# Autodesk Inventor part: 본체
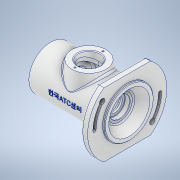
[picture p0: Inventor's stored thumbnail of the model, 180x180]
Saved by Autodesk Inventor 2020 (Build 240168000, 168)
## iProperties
Created: 2022-05
Part Number: 본체
Material: 알루미늄 6061
Document SubType Name: Modeling
Designer: Student
Density: 2.7 g/cm^3
Appearance: 알루미늄 - 평지
Mass: 694.173 g
Surface Area: 619.363 cm^2
Volume: 257.101 cm^3
Author: Student
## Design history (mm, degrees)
sketch "스케치1"
  geometry: L1 (-108.341, 0)-(108.341, 0); L2 (-56, 22.5)-(-48, 22.5); L3 (-48, 22.5)-(-48, 24); L4 (-48, 24)-(-45, 24); L5 (-45, 24)-(-45, 22.5); L6 (-45, 22.5)-(-34, 22.5); L7 (-34, 22.5)-(-34, 17.5); L8 (-34, 17.5)-(-31.75, 17.5); L9 (-31.75, 17.5)-(-31.75, 18.5); L10 (-31.75, 18.5)-(-30, 18.5); L11 (-30, 18.5)-(-30, 17.5); L12 (-30, 17.5)-(-19, 17.5); L13 (-19, 17.5)-(-19, 27); L14 (-19, 27)-(19, 27); L15 (19, 27)-(19, 17.5); L16 (19, 17.5)-(30, 17.5); L17 (30, 17.5)-(30, 15); L18 (30, 15)-(35, 15); L19 (35, 15)-(35, 11); L20 (35, 11)-(37.7, 11); L21 (37.7, 11)-(37.7, 15); L22 (37.7, 15)-(45, 15); L23 (46, 32)-(-56, 32); L24 (-56, 32)-(-56, 22.5); L25 (46, 32)-(46, 58); L26 (46, 58)-(56, 58); L27 (56, 58)-(56, 36); L28 (56, 36)-(59, 36); L29 (59, 36)-(59, 30); L30 (59, 30)-(45, 20); L31 (45, 20)-(45, 15); 3 further points
  constraints: 62 end point, 23 perpendicular, 4 point on line, 2 horizontal, 2 midpoint, 2 vertical, 1 coincident, 1 vertical alignment
  dimensions: "d1" = 45 diameter of L2 L1; "d2" = 48 diameter of L4 L1; "d3" = 45 diameter of L6 L1; "d4" = 35 diameter of L8 L1; "d5" = 37 diameter of L10 L1; "d6" = 54 diameter of L14 L1; "d7" = 30 diameter of L18 L1; "d8" = 22 diameter of L20 L1; "d9" = 30 diameter of L22 L1; "d10" = 64 diameter of L23 L1; "d11" = 8 distance of L2.start L2.end; "d12" = 3 distance of L3.end L4.end; "d13" = 22 distance from line of L6.end L24; "d16" = 1.75 distance of L9.end L10.end; "d17" = 2.25 distance of L7.end L8.end; "d18" = 11 distance of L11.end L12.end; "d19" = 38 distance of L13.end L14.end; "d20" = 11 distance of L15.end L16.end; "d21" = 5 distance of L17.end L18.end; "d22" = 7.3 distance of L21.end L22.end; "d25" = 216.68188 distance of L1.start L1.end; "d26" = 116 diameter of L26 L1; "d27" = 3 distance of L27.end L28.end; "d28" = 13 distance between parallel lines of L29 L25; "d29" = 14 distance between parallel lines of L29 L31; "d30" = 60 diameter of L29.end L1; "d31" = 72 diameter of L28.end L1; "d32" = 115 distance between parallel lines of L29 L24; "d33" = 40 diameter of L30.end L1
revolve "회전1" sketch "스케치1" stored, may be unused: angle "d34" = 90 deg
node "작업 평면1"
sketch "스케치2"
  geometry: C1 r 25 at (0, 0); C2 r 16 at (0, 0); 1 further point
  constraints: 2 centre point, 2 coincident
  dimensions: "d36" = 50 diameter of C1; "d37" = 32 diameter of C2
extrude "돌출1" join sketch "스케치2" stored distance "d38" = 10; taper "d39" = 10 deg
sketch "스케치3"
  geometry: 2 further points
  constraints: 1 other
extrude "돌출2" cut sketch "스케치3" stored distance "d40" = 10; taper "d41" = 0 deg
sketch "스케치4" dims "d42" = 41
  geometry: 3 further points
  constraints: 2 vertical alignment, 1 coincident, 2 other
hole "구멍1" sketch "스케치4" at (0, 20.5) diameter "d43" = 2.459; stored, may be unused: countersink angle "d47" = 90 deg, drill point angle "d49" = 118 deg; dims "d44" = 6, "d45" = 4, "d46" = 2, "d48" = 8
chamfer "모따기1" distance "d53" = 1; stored, may be unused: second distance "d54" = 2, angle "d55" = 45 deg
sketch "스케치5"
  geometry: L1 (-100.618, 47)-(100.618, 47); L2 (100.618, -47)-(-100.618, -47); L3 (-100.618, 47)-(-100.618, 99.417); L4 (-100.618, 99.417)-(100.618, 99.417); L5 (100.618, 99.417)-(100.618, 47); L6 (100.618, -47)-(100.618, -96); L7 (100.618, -96)-(-100.618, -96); L8 (-100.618, -96)-(-100.618, -47); 3 further points
  constraints: 16 end point, 4 perpendicular, 2 midpoint, 2 point on line, 2 vertical alignment, 1 horizontal, 1 parallel, 1 vertical
  dimensions: "d56" = 94 distance between parallel lines of L2 L1; "d57" = 47 distance from line of point (0, 0) L1; "d59" = 90 deg angle of L5 L7; "d60" = 201.23562 distance between parallel lines of L3 L5; "d61" = 52.41734 distance between parallel lines of L4 L1
extrude "돌출3" cut sketch "스케치5" distance "d62" = 10; taper "d63" = 0 deg
sketch "스케치6"
  geometry: L1 (0, 0)-(58, 0); L2 (0, 0)-(36.77, 30.854); L3 (0, 0)-(-36.77, -30.854); A1 r 48 centre (0, 0) between (36.77, 30.854) and (-36.77, -30.854); A2 r 4 centre (36.77, 30.854) between (33.706, 28.283) and (39.834, 33.425); A3 r 4 centre (-36.77, -30.854) between (-39.834, -33.425) and (-32.885, -31.806); A4 r 58 centre (0, 0) between (33.985, -47) and (33.985, 47) reference; A5 r 4 centre (48, 0) between (44, 0) and (52, 0); A6 r 4 centre (-48, 0) between (-44, 0) and (-52, 0); A7 r 52 centre (0, 0) between (-52, 0) and (-39.834, -33.425); A8 r 52 centre (0, 0) between (52, 0) and (39.834, 33.425); A9 r 44 centre (0, 0) between (-44, 0) and (-33.706, -28.283); A10 r 44 centre (0, 0) between (44, 0) and (33.706, 28.283); A11 r 2.25 centre (48, 0) between (45.75, 0) and (50.25, 0); A12 r 2.25 centre (-48, 0) between (-45.75, 0) and (-50.25, 0); A13 r 45.75 centre (0, 0) between (-45.75, 0) and (-32.885, -31.806); A14 r 45.75 centre (0, 0) between (45.75, 0) and (32.885, 31.806); A15 r 50.25 centre (0, 0) between (-50.25, 0) and (-36.233, -34.818); A16 r 50.25 centre (0, 0) between (50.25, 0) and (36.233, 34.818); 6 further points
  constraints: 36 point on circle, 15 centre point, 6 end point, 3 coincident, 2 point on line, 1 horizontal, 1 horizontal alignment
  dimensions: "d64" = 96 diameter of A1; "d65" = 8 diameter of A2; "d66" = 8 diameter of A3; "d67" = 40 deg angle of L1 L2; "d68" = 140 deg angle of L1 L3; "d69" = 8 diameter of A5; "d72" = 8 diameter of A6; "d73" = 52 radius of A7; "d74" = 44 radius of A9; "d75" = 52 radius of A8; "d76" = 44 radius of A10; "d77" = 4.5 diameter of A11; "d78" = 4.5 diameter of A12; "d83" = 50.25 radius of A15; "d84" = 45.75 radius of A13; "d85" = 50.25 radius of A16; "d86" = 45.75 radius of A14
extrude "돌출4" cut sketch "스케치6" extent not by distance; stored distance "d79" = 0; taper "d80" = 0 deg
extrude "돌출5" cut sketch "스케치6" distance "d87" = 4.4; taper "d88" = 0 deg
extrude "돌출6" cut sketch "스케치6" extent not by distance; stored distance "d89" = 0; taper "d90" = 0 deg
node "작업 평면2"
sketch "스케치7"
  geometry: L1 (59, -36)-(59, 36) reference; 3 further points
  constraints: 1 horizontal alignment, 1 midpoint, 1 other
  dimensions: "d92" = 62 distance from line of L1 point (-3, 0)
feature "엠보싱1" sketch "스케치7" dims "d1" = 45, "d2" = 48, "d3" = 45, "d4" = 35, "d5" = 37, "d6" = 54, "d7" = 30, "d8" = 22, "d9" = 30, "d10" = 64, "d11" = 8, "d12" = 3, "d13" = 22, "d16" = 1.75, "d17" = 2.25, "d18" = 11, "d19" = 38, "d20" = 11, "d21" = 5, "d22" = 7.3, "d25" = 216.68188, "d26" = 116, "d27" = 3, "d28" = 13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
feature "스레드1" dims "d95" = 8, "d96" = 0
fillet "모깎기1" dims "d97" = 3
fillet "모깎기2" dims "d98" = 3
chamfer "모따기2" distance "d99" = 1; stored, may be unused: second distance "d100" = 2, angle "d101" = 45 deg
fillet "모깎기3" dims "d102" = 3
fillet "모깎기4" dims "d103" = 0.5
fillet "모깎기5" dims "d104" = 0.6
chamfer "모따기3" distance "d105" = 1; stored, may be unused: second distance "d106" = 2, angle "d107" = 45 deg
chamfer "모따기4" distance "d108" = 0.7; stored, may be unused: second distance "d109" = 2, angle "d110" = 30 deg
fillet "모깎기6" dims "d111" = 3
fillet "모깎기7" dims "d112" = 3
node "솔리드1"
pattern_circular "원형 패턴1" dims angle "d51" = 360 deg
node "투영된 루프1"
feature "A9D066F2-1C7D-4E18-AEED-F7BC21143FA4" dims "d43" = 2.459, "d44" = 6, "d45" = 4, "d46" = 2, "d47" = 90 deg, "d48" = 8, "d49" = 118 deg
other parameters: "d35" = 38, "d70" = 4, "d71" = 4, "d81" = 2.25, "d82" = 2.25, "d91" = 43.25
